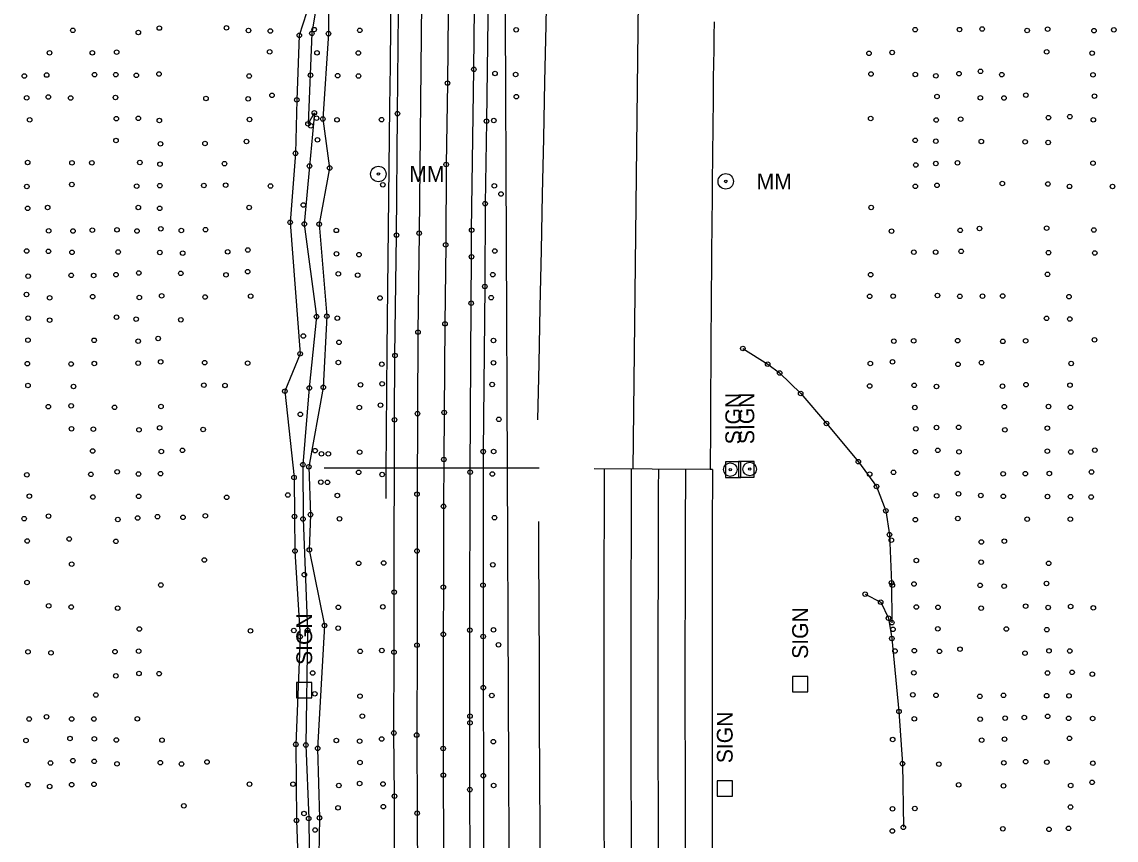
# Model space of a CAD drawing. Extents: x 20503438 to 20508873, y 7964251 to 7984667.
# Drawn here: x 20506380.3 to 20506865.5, y 7965237.1 to 7965600.1 of the extents above; entities that cross this region are included whole.
import ezdxf

# ---------------------------------------------------------------- set-up
doc = ezdxf.new("R2010")
doc.units = 0
for name, color, linetype in [('PhoSignTrussOverhead', 7, 'Continuous'), ('SurBreakLine', 7, 'Continuous'), ('SurDrainageArrowDown', 7, 'Continuous'), ('SurEdgeRoadPaved', 7, 'Continuous'), ('SurEdgeShoulderPaved', 7, 'Continuous'), ('SurGuardRailCable', 7, 'Continuous'), ('SurPointsNonDTM', 7, 'Continuous'), ('SurRoadPoints', 7, 'Continuous'), ('SurSurveyPoints', 7, 'Continuous'), ('SurWetlands', 7, 'Continuous')]:
    doc.layers.add(name, color=color, linetype=linetype)

msp = doc.modelspace()

# ---------------------------------------------------------------- linework, layer by layer
at = {"layer": 'PhoSignTrussOverhead'}
msp.add_line((20506514.44, 7965402.17), (20506609.7, 7965402.17), dxfattribs=at)
at = {"layer": 'SurBreakLine'}
for points in [[(20506660.03, 7966157.63), (20506658.3, 7966009.76), (20506658.04, 7965973.78), (20506656.47, 7965856.82), (20506651.2, 7965401.69)], [(20506522.39, 7965700.71), (20506522, 7965700.32), (20506516.56, 7965699.39), (20506518.84, 7965688.49), (20506515.01, 7965666.88), (20506518.2, 7965645.46), (20506516.16, 7965620.24), (20506516.31, 7965594.85), (20506513.79, 7965556.99), (20506516.81, 7965535.24), (20506512.19, 7965510.34), (20506515.52, 7965469.48), (20506513.97, 7965437.92), (20506507.59, 7965402.71), (20506508.3, 7965381.45), (20506507.78, 7965365.83), (20506514.49, 7965332.27), (20506511.48, 7965277.77), (20506512.31, 7965246.93), (20506511.6, 7965205.59), (20506511.79, 7965203.63)], [(20506511.46, 7965619.33), (20506503.35, 7965594.08), (20506502.22, 7965565.46), (20506501.65, 7965541.77), (20506499.26, 7965511.13), (20506503.71, 7965452.81), (20506496.96, 7965436.26), (20506501.03, 7965397.95), (20506501.18, 7965380.68), (20506501.43, 7965365.34), (20506503.7, 7965327.33), (20506501.82, 7965279.54), (20506502.13, 7965245.82), (20506503.57, 7965205.44), (20506503.7, 7965203.31)], [(20506569.39, 7965603.88), (20506569.1, 7965572.92), (20506568.45, 7965536.8), (20506568.27, 7965501.17), (20506567.94, 7965466.14), (20506567.58, 7965426.78), (20506567.45, 7965405.97), (20506567.32, 7965385.16), (20506567.23, 7965349.31), (20506567.21, 7965328.34), (20506567.14, 7965277.73), (20506567.21, 7965265.93), (20506567.51, 7965206.56), (20506567.54, 7965202.77)]]:
    msp.add_lwpolyline(points, dxfattribs=at)
for radius in [22877.31, 22865.31]:
    msp.add_arc((20529527.68, 7965307.24), radius, 179.763399, 181.192225, dxfattribs=at)
at = {"layer": 'SurDrainageArrowDown'}
for points in [[(20506609.14, 7965423.53), (20506609.66, 7965448.52), (20506610.19, 7965473.52), (20506610.72, 7965498.73), (20506611.24, 7965523.51), (20506611.76, 7965548.5), (20506612.29, 7965573.49), (20506612.82, 7965598.63), (20506613.33, 7965623.29), (20506613.86, 7965648.48), (20506613.96, 7965653.23)], [(20506512.75, 7965618.39), (20506508.94, 7965594.99), (20506507.21, 7965554.81), (20506510.03, 7965559.76), (20506507.85, 7965536.13), (20506505.57, 7965510.38), (20506511, 7965469.31), (20506507.78, 7965437.68), (20506504.95, 7965403.63), (20506505.01, 7965379.53), (20506507.03, 7965330.13), (20506506.23, 7965279.25), (20506507.51, 7965246.68), (20506507.98, 7965205.94), (20506507.99, 7965183.58), (20506506.45, 7965157.25), (20506507.19, 7965112.35), (20506505.61, 7965065.42), (20506505.71, 7965016.95)], [(20506610.82, 7965065.24), (20506610.71, 7965090.24), (20506610.61, 7965115.23), (20506610.51, 7965140.23), (20506610.41, 7965165.23), (20506610.31, 7965190.23), (20506610.21, 7965215.23), (20506610.1, 7965240.23), (20506610, 7965265.23), (20506609.9, 7965290.23), (20506609.8, 7965315.23), (20506609.7, 7965340.23), (20506609.6, 7965365.23), (20506609.54, 7965378.43)]]:
    msp.add_lwpolyline(points, dxfattribs=at)
at = {"layer": 'SurEdgeRoadPaved'}
msp.add_line((20506685.57, 7965401.56), (20506634.11, 7965401.78), dxfattribs=at)
for points in [[(20506562.98, 7966069.12), (20506561.69, 7965956.65), (20506561.36, 7965927.21), (20506561.02, 7965904.12), (20506560.12, 7965843.51), (20506559.8, 7965821.05), (20506559.37, 7965785.5), (20506558.21, 7965668.14), (20506558.03, 7965647.17), (20506557.54, 7965608.72), (20506556.5, 7965506.31), (20506555.98, 7965462.45), (20506555.76, 7965426.25), (20506555.55, 7965390.53), (20506555.55, 7965365.32), (20506555.55, 7965323.6), (20506555.42, 7965283.68), (20506555.63, 7965249), (20506555.73, 7965220.22), (20506555.85, 7965201.63)], [(20506579.33, 7965201.74), (20506579.06, 7965228.35), (20506578.95, 7965259.46), (20506579.02, 7965289.12), (20506579.03, 7965292.09), (20506578.95, 7965330.25), (20506579.12, 7965400.3), (20506579.58, 7965475.25), (20506579.7, 7965495.86), (20506579.77, 7965507.64), (20506580.77, 7965579.04), (20506582.18, 7965713.39), (20506584.15, 7965857.73), (20506584.51, 7965883.12), (20506584.95, 7965922.01), (20506585.27, 7965953.21), (20506585.61, 7965985.81), (20506586.02, 7966017.66)]]:
    msp.add_lwpolyline(points, dxfattribs=at)
for centre, major_axis, start_param, end_param in [((20529528.34, 7965306.75), (15930.49, -16371.54), 3.927809, 3.936499), ((20529528.35, 7965306.75), (16385.16, -15983.87), 3.910449, 3.935387), ((20529528.35, 7965306.75), (16358.96, -15959.17), 3.910476, 3.935414)]:
    msp.add_ellipse(centre, major_axis=major_axis, ratio=0.999988, start_param=start_param, end_param=end_param, dxfattribs=at)
at = {"layer": 'SurEdgeShoulderPaved'}
msp.add_line((20506686.57, 7965401.56), (20506685.57, 7965401.56), dxfattribs=at)
for points in [[(20506545.59, 7965201.59), (20506545.55, 7965219.53), (20506545.56, 7965256.58), (20506545.28, 7965284.63), (20506545.36, 7965320.45), (20506545.43, 7965347.11), (20506545.59, 7965423.56), (20506545.77, 7965452.03), (20506546.43, 7965505.49), (20506546.86, 7965559.32), (20506548.13, 7965680.05), (20506548.89, 7965738.14), (20506549.41, 7965796.65), (20506550.26, 7965848.19), (20506551.65, 7965956.18), (20506552.19, 7965996.51), (20506552.57, 7966028.45), (20506552.68, 7966057.72)], [(20506592.19, 7966059.31), (20506591.79, 7966030.9), (20506591.18, 7965975.25), (20506590.93, 7965954.62), (20506589.59, 7965843.55), (20506588.16, 7965735.35), (20506587.68, 7965699.72), (20506587.42, 7965658.24), (20506587.16, 7965625.38), (20506586.88, 7965601.51), (20506586.38, 7965556.01), (20506585.73, 7965519.42), (20506585.6, 7965482.7), (20506584.9, 7965409.44), (20506584.81, 7965350.17), (20506584.84, 7965327.41), (20506584.92, 7965304.74), (20506584.98, 7965265.69), (20506584.99, 7965225.89), (20506585.23, 7965201.77)]]:
    msp.add_lwpolyline(points, dxfattribs=at)
msp.add_ellipse((20529528.35, 7965306.75), major_axis=(16351.94, -15949.18), ratio=0.999988, start_param=3.910378, end_param=3.935316, dxfattribs=at)
at = {"layer": 'SurGuardRailCable'}
for points in [[(20506613.34, 7964252.79), (20506601.5, 7964822.04), (20506598.64, 7964984.08), (20506597.55, 7965074.02), (20506596.61, 7965201.81), (20506594.34, 7965701.8), (20506594.71, 7965733.27), (20506595.45, 7965806.52), (20506596.03, 7965869.84), (20506597.23, 7965978.92), (20506600.18, 7966186.78), (20506601.51, 7966279.91), (20506601.63, 7966286.68)], [(20506544.5, 7965688.68), (20506544.37, 7965670.68), (20506544.23, 7965652.66), (20506544.02, 7965624.87), (20506543.77, 7965598.66), (20506543.59, 7965580.66), (20506543.41, 7965562.43), (20506542.7, 7965508.66), (20506542.13, 7965454.69), (20506541.73, 7965400.68), (20506541.77, 7965388.69)]]:
    msp.add_lwpolyline(points, dxfattribs=at)
at = {"layer": 'SurPointsNonDTM'}
for centre in [(20506508.31, 7965576.41), (20506508.47, 7965553.92), (20506592.77, 7965523.74), (20506505.14, 7965518.82), (20506505.14, 7965460.72), (20506700.06, 7965455.18), (20506711.06, 7965448.26), (20506716.34, 7965444.32), (20506725.67, 7965435.22), (20506503.78, 7965425.97), (20506591.83, 7965423.75), (20506737.13, 7965421.9), (20506751.27, 7965404.97), (20506498.27, 7965390.18), (20506759.33, 7965393.95), (20506763.44, 7965383.19), (20506765.03, 7965372.58), (20506505.61, 7965354.83), (20506765.93, 7965351.22), (20506754.26, 7965346.22), (20506761.15, 7965342.67), (20506764.62, 7965335.54), (20506766.12, 7965333.53), (20506591.69, 7965323.75), (20506766.09, 7965326.51), (20506509.29, 7965311.22), (20506769.25, 7965294.11), (20506770.8, 7965270.97), (20506505.4, 7965248.86), (20506771.22, 7965242.76)]:
    msp.add_circle(centre, 1, dxfattribs=at)
at = {"layer": 'SurRoadPoints'}
for points in [[(20506699.21, 7965401.42), (20506699.21, 7965401.42), (20506699.21, 7965404.85), (20506692.35, 7965404.85), (20506692.35, 7965397.99), (20506699.21, 7965397.99), (20506699.21, 7965401.42)], [(20506705.03, 7965401.56), (20506705.03, 7965401.56), (20506705.03, 7965404.99), (20506698.17, 7965404.99), (20506698.17, 7965398.13), (20506705.03, 7965398.13), (20506705.03, 7965401.56)], [(20506728.85, 7965306.3), (20506728.85, 7965306.3), (20506728.85, 7965309.73), (20506721.99, 7965309.73), (20506721.99, 7965302.87), (20506728.85, 7965302.87), (20506728.85, 7965306.3)], [(20506508.96, 7965303.6), (20506508.96, 7965303.6), (20506508.96, 7965307.03), (20506502.1, 7965307.03), (20506502.1, 7965300.17), (20506508.96, 7965300.17), (20506508.96, 7965303.6)], [(20506695.44, 7965260), (20506695.44, 7965260), (20506695.44, 7965263.43), (20506688.58, 7965263.43), (20506688.58, 7965256.57), (20506695.44, 7965256.57), (20506695.44, 7965260)]]:
    msp.add_lwpolyline(points, dxfattribs=at)
for centre, radius in [((20506538.42, 7965532.57), 3.43), ((20506538.42, 7965532.57), 0.571), ((20506692.45, 7965529.31), 3.43), ((20506692.45, 7965529.31), 0.571), ((20506694.48, 7965401.45), 3), ((20506694.48, 7965401.45), 0.5), ((20506703.08, 7965401.68), 3), ((20506703.08, 7965401.68), 0.5)]:
    msp.add_circle(centre, radius, dxfattribs=at)
at = {"layer": 'SurSurveyPoints'}
for centre in [(20506402.92, 7965596.33), (20506431.99, 7965595.39), (20506441.28, 7965597.32), (20506471.04, 7965597.4), (20506480.83, 7965596.23), (20506490.49, 7965596.02), (20506503.35, 7965594.08), (20506508.94, 7965594.99), (20506509.95, 7965596.65), (20506516.31, 7965594.85), (20506530.15, 7965596.29), (20506599.52, 7965596.57), (20506776.44, 7965596.6), (20506796.13, 7965596.65), (20506806.15, 7965596.88), (20506826.08, 7965596.23), (20506835.19, 7965596.83), (20506855.75, 7965596.19), (20506864.55, 7965596.56), (20506392.61, 7965586.34), (20506411.6, 7965586.37), (20506422.33, 7965586.63), (20506490.22, 7965586.78), (20506511.17, 7965586.37), (20506529.55, 7965586.26), (20506755.95, 7965586.12), (20506766.23, 7965586.51), (20506834.78, 7965586.8), (20506854.91, 7965586.22), (20506580.77, 7965579.04), (20506381.43, 7965576.07), (20506391.34, 7965576.47), (20506412.56, 7965576.65), (20506421.96, 7965576.62), (20506431.07, 7965576.38), (20506441.14, 7965576.94), (20506481.1, 7965576.05), (20506520.34, 7965576.18), (20506529.59, 7965576.07), (20506590.14, 7965577.19), (20506599.29, 7965576.74), (20506756.84, 7965576.92), (20506776.5, 7965576.76), (20506785.63, 7965576.15), (20506795.91, 7965577.1), (20506805.42, 7965578.14), (20506814.85, 7965576.63), (20506855.28, 7965576.58), (20506569.1, 7965572.92), (20506382.47, 7965566.37), (20506392.04, 7965566.75), (20506401.94, 7965566.32), (20506421.82, 7965566.51), (20506461.94, 7965566.1), (20506480.69, 7965565.9), (20506491.24, 7965567.49), (20506502.22, 7965565.46), (20506599.61, 7965566.88), (20506786.11, 7965566.96), (20506805.37, 7965566.4), (20506815.83, 7965566.33), (20506825.54, 7965567.59), (20506855.93, 7965567.14), (20506510.03, 7965559.76), (20506383.81, 7965556.6), (20506422.22, 7965557.16), (20506431.94, 7965557.25), (20506441.3, 7965556.29), (20506481.3, 7965556.76), (20506507.21, 7965554.81), (20506511, 7965557.35), (20506513.79, 7965556.99), (20506520.05, 7965556.65), (20506539.83, 7965556.71), (20506546.86, 7965559.32), (20506586.38, 7965556.01), (20506589.58, 7965556.29), (20506756.73, 7965557.2), (20506785.78, 7965556.51), (20506796.59, 7965556.91), (20506835.53, 7965557.58), (20506845.03, 7965558.02), (20506855.42, 7965556.64), (20506422.06, 7965547.42), (20506441.77, 7965545.98), (20506461.5, 7965546.13), (20506479.91, 7965546.99), (20506511.38, 7965547.76), (20506776.48, 7965547.51), (20506785.62, 7965547.12), (20506805.75, 7965547.03), (20506825.2, 7965546.85), (20506835.42, 7965546.56), (20506501.65, 7965541.77), (20506382.89, 7965537.71), (20506402.52, 7965537.53), (20506411.37, 7965537.53), (20506432.65, 7965537.68), (20506441.57, 7965536.91), (20506470.16, 7965537.17), (20506507.85, 7965536.13), (20506516.81, 7965535.24), (20506568.45, 7965536.8), (20506776.7, 7965536.59), (20506785.61, 7965537.21), (20506795.23, 7965537.54), (20506855.29, 7965537.39), (20506382.5, 7965527.04), (20506402.47, 7965527.94), (20506431.23, 7965527.18), (20506441.51, 7965527.4), (20506461.04, 7965527.47), (20506470.72, 7965527.6), (20506490.58, 7965527.23), (20506540.39, 7965527.8), (20506589.82, 7965527.32), (20506776.5, 7965527.12), (20506786.11, 7965527.55), (20506815.07, 7965528.36), (20506835.3, 7965528.15), (20506844.86, 7965527.08), (20506863.97, 7965527.07), (20506382.89, 7965517.37), (20506391.74, 7965517.69), (20506431.95, 7965517.75), (20506441.46, 7965517.34), (20506481.09, 7965517.75), (20506585.73, 7965519.42), (20506756.94, 7965517.75), (20506499.26, 7965511.13), (20506392.23, 7965507.39), (20506402.97, 7965507.27), (20506411.54, 7965507.67), (20506422.52, 7965507.84), (20506431.4, 7965507.3), (20506441.92, 7965508.29), (20506451.03, 7965507.54), (20506461.74, 7965507.86), (20506505.57, 7965510.38), (20506512.19, 7965510.34), (20506519.76, 7965507.56), (20506556.5, 7965506.31), (20506579.77, 7965507.64), (20506765.97, 7965507.23), (20506796.42, 7965507.59), (20506804.94, 7965508.39), (20506834.74, 7965508.55), (20506855.66, 7965507.75), (20506546.43, 7965505.49), (20506382.44, 7965498.45), (20506392.1, 7965498.27), (20506402.58, 7965497.82), (20506423.04, 7965497.98), (20506441.51, 7965497.79), (20506451.66, 7965497.5), (20506471.61, 7965498.09), (20506480.52, 7965498.84), (20506519.82, 7965497.18), (20506529.84, 7965496.81), (20506568.27, 7965501.17), (20506590.03, 7965498.4), (20506775.85, 7965497.91), (20506785.54, 7965497.94), (20506796.84, 7965498.31), (20506835.57, 7965497.71), (20506856.09, 7965497.57), (20506579.7, 7965495.86), (20506383.13, 7965487.25), (20506402.22, 7965487.63), (20506412.14, 7965487.53), (20506422.07, 7965487.96), (20506432.16, 7965488.68), (20506450.79, 7965488.55), (20506470.82, 7965487.82), (20506480.48, 7965489.24), (20506520.63, 7965488.28), (20506529.26, 7965487.74), (20506589.14, 7965487.95), (20506756.69, 7965487.94), (20506835.11, 7965488.07), (20506585.6, 7965482.7), (20506382.36, 7965479.14), (20506392.62, 7965477.64), (20506411.74, 7965478.14), (20506432.39, 7965477.81), (20506442.3, 7965478.54), (20506461.57, 7965478.01), (20506481.8, 7965478.41), (20506539.12, 7965477.57), (20506588.44, 7965477.7), (20506756.26, 7965478.29), (20506766.65, 7965478.41), (20506786.32, 7965478.68), (20506796.25, 7965478.34), (20506806.31, 7965478.39), (20506815.23, 7965478.45), (20506844.64, 7965478.15), (20506579.58, 7965475.25), (20506383.11, 7965468.66), (20506392.63, 7965467.72), (20506422.28, 7965469.05), (20506430.97, 7965468.21), (20506450.83, 7965467.92), (20506511, 7965469.31), (20506515.52, 7965469.48), (20506520.19, 7965468.65), (20506834.71, 7965468.54), (20506845, 7965468.25), (20506555.98, 7965462.45), (20506567.94, 7965466.14), (20506383.01, 7965458.87), (20506412.4, 7965458.83), (20506431.92, 7965458.41), (20506440.78, 7965459.64), (20506520.93, 7965457.88), (20506589.43, 7965458.73), (20506767, 7965458.46), (20506775.81, 7965458.58), (20506795.28, 7965458.65), (20506815.31, 7965458.32), (20506825.43, 7965458.57), (20506855.98, 7965459.01), (20506503.71, 7965452.81), (20506382.78, 7965448.42), (20506402.15, 7965448.32), (20506412.43, 7965448.49), (20506431.88, 7965448.68), (20506441.88, 7965449.23), (20506461.38, 7965448.92), (20506480.44, 7965448.66), (20506520.68, 7965448.95), (20506539.92, 7965448.2), (20506545.77, 7965452.03), (20506589.44, 7965448.84), (20506756.55, 7965448.51), (20506766.38, 7965449.23), (20506795.46, 7965448.18), (20506805.87, 7965448.86), (20506845.63, 7965448.54), (20506383.01, 7965438.77), (20506403.24, 7965438.34), (20506461.04, 7965438.89), (20506470.4, 7965438.78), (20506530.52, 7965439.09), (20506540.06, 7965439.51), (20506588.88, 7965439.2), (20506756.3, 7965438.53), (20506776.03, 7965438.84), (20506785.88, 7965438.31), (20506815.16, 7965438.43), (20506825.57, 7965439.13), (20506845.09, 7965438.87), (20506496.96, 7965436.26), (20506507.78, 7965437.68), (20506513.97, 7965437.92), (20506392.03, 7965429.37), (20506402.2, 7965429.75), (20506421.43, 7965429.05), (20506442.05, 7965429.46), (20506529.97, 7965429), (20506539.32, 7965430.02), (20506776.28, 7965428.97), (20506815.98, 7965429.4), (20506835.56, 7965429.42), (20506845.25, 7965429.05), (20506555.76, 7965426.25), (20506567.58, 7965426.78), (20506402.34, 7965419.57), (20506412.03, 7965419.37), (20506432.25, 7965419.08), (20506441.42, 7965420.01), (20506460.68, 7965419.23), (20506545.59, 7965423.56), (20506776.72, 7965419.53), (20506785.89, 7965420.1), (20506795.73, 7965420.2), (20506816.23, 7965419.1), (20506835.06, 7965419.8), (20506411.72, 7965409.69), (20506442.15, 7965409.47), (20506451.53, 7965409.97), (20506510.36, 7965409.82), (20506530.11, 7965409.18), (20506584.9, 7965409.44), (20506589.53, 7965409.5), (20506776.5, 7965409.42), (20506786.46, 7965410.03), (20506795.87, 7965409.35), (20506835.08, 7965409.64), (20506845.46, 7965409.29), (20506856.13, 7965410.06), (20506513.17, 7965408.45), (20506516.2, 7965408.44), (20506567.45, 7965405.97), (20506410.93, 7965399.33), (20506422.61, 7965400.47), (20506432.04, 7965399.47), (20506441.82, 7965399.64), (20506504.95, 7965403.63), (20506507.59, 7965402.71), (20506529.66, 7965400.27), (20506579.12, 7965400.3), (20506588.97, 7965399.47), (20506756.25, 7965399.46), (20506766.84, 7965400.24), (20506795.15, 7965399.8), (20506815.44, 7965399.58), (20506825.31, 7965399.64), (20506835.95, 7965399.7), (20506854.63, 7965400.36), (20506382.55, 7965399.13), (20506501.03, 7965397.95), (20506512.89, 7965395.9), (20506515.83, 7965395.79), (20506540.11, 7965399.24), (20506383.64, 7965389.64), (20506432.09, 7965389.6), (20506520.23, 7965389.94), (20506555.55, 7965390.53), (20506776.53, 7965390.45), (20506786.01, 7965389.8), (20506795.66, 7965390.69), (20506805.54, 7965390), (20506815.53, 7965389.6), (20506411.83, 7965389.29), (20506471.16, 7965389.14), (20506567.32, 7965385.16), (20506835.14, 7965389.48), (20506845.35, 7965389.44), (20506854.5, 7965389.3), (20506392.16, 7965380.83), (20506431.66, 7965379.96), (20506440.47, 7965380.55), (20506451.8, 7965380.26), (20506461.69, 7965380.93), (20506501.18, 7965380.68), (20506508.3, 7965381.45), (20506589.89, 7965380.12), (20506381.33, 7965379.67), (20506422.86, 7965379.33), (20506505.01, 7965379.53), (20506521.16, 7965379.63), (20506776.55, 7965379.22), (20506795.35, 7965379.77), (20506826.14, 7965379.45), (20506845.23, 7965379.46), (20506401.33, 7965370.69), (20506382.71, 7965369.8), (20506422.02, 7965369.65), (20506501.43, 7965365.34), (20506507.78, 7965365.83), (20506765.87, 7965370.15), (20506805.79, 7965369.32), (20506815.98, 7965369.67), (20506461.21, 7965361.35), (20506555.55, 7965365.32), (20506776.98, 7965361.16), (20506402.42, 7965359.48), (20506529.68, 7965359.89), (20506540.77, 7965360.03), (20506589.17, 7965359.24), (20506805.72, 7965360.37), (20506835.61, 7965359.87), (20506382.59, 7965351.38), (20506834.67, 7965350.96), (20506441.95, 7965350.25), (20506545.43, 7965347.11), (20506567.23, 7965349.31), (20506584.81, 7965350.17), (20506766.35, 7965350.15), (20506775.94, 7965350.7), (20506805.23, 7965350.13), (20506815.88, 7965349.75), (20506392.24, 7965341.01), (20506402.22, 7965340.49), (20506422.83, 7965340), (20506520.66, 7965340.37), (20506540.37, 7965340.55), (20506776.99, 7965340.51), (20506786.55, 7965340.32), (20506805.72, 7965339.97), (20506825.44, 7965340.83), (20506835.39, 7965340.31), (20506845.38, 7965340.74), (20506855.43, 7965340.09), (20506514.49, 7965332.27), (20506432.41, 7965330.71), (20506481.68, 7965329.89), (20506500.92, 7965330.07), (20506503.7, 7965327.33), (20506507.03, 7965330.13), (20506520.59, 7965331.14), (20506567.21, 7965328.34), (20506578.95, 7965330.25), (20506584.84, 7965327.41), (20506589.45, 7965330.33), (20506766.63, 7965330.58), (20506786.47, 7965330.82), (20506816.86, 7965330.72), (20506834.83, 7965330.46), (20506555.55, 7965323.6), (20506796.3, 7965321.76), (20506383.07, 7965320.6), (20506393.23, 7965320.17), (20506421.65, 7965320.71), (20506432.12, 7965320.91), (20506530.34, 7965320.81), (20506539.93, 7965321.21), (20506545.36, 7965320.45), (20506767.5, 7965321.01), (20506776.08, 7965321.14), (20506787.21, 7965320.82), (20506825.17, 7965320.02), (20506835.76, 7965321.02), (20506845, 7965321.01), (20506422, 7965309.94), (20506432.24, 7965311.02), (20506441.18, 7965310.91), (20506775.82, 7965311.29), (20506835.14, 7965311.21), (20506846.04, 7965311.54), (20506855.01, 7965310.73), (20506584.92, 7965304.74), (20506413.11, 7965301.48), (20506510.21, 7965302), (20506530.26, 7965300.93), (20506588.69, 7965301.25), (20506775.39, 7965301.52), (20506785.7, 7965301.34), (20506805.13, 7965300.88), (20506815.63, 7965301.3), (20506834.73, 7965301.13), (20506844.67, 7965301.12), (20506383.56, 7965290.78), (20506391.25, 7965291.81), (20506402.4, 7965290.81), (20506412.26, 7965290.83), (20506431.55, 7965290.91), (20506531.28, 7965292.06), (20506579.02, 7965289.12), (20506579.03, 7965292.09), (20506776.05, 7965290.92), (20506805.27, 7965290.72), (20506816.36, 7965291.21), (20506824.82, 7965291.48), (20506835.19, 7965292.01), (20506844.5, 7965291.12), (20506855.12, 7965291.05), (20506545.28, 7965284.63), (20506555.42, 7965283.68), (20506382.15, 7965281.28), (20506401.64, 7965282.13), (20506412.47, 7965282.02), (20506422.2, 7965281.49), (20506442.45, 7965281.45), (20506501.82, 7965279.54), (20506506.23, 7965279.25), (20506519.79, 7965281.31), (20506530.11, 7965280.96), (20506539.89, 7965281.92), (20506589.37, 7965280.78), (20506766.49, 7965281.68), (20506805.94, 7965281.43), (20506816.09, 7965281.87), (20506844.85, 7965282.22), (20506511.48, 7965277.77), (20506567.14, 7965277.73), (20506393, 7965271.3), (20506402.95, 7965272.35), (20506412.41, 7965272.04), (20506422.48, 7965270.93), (20506441.72, 7965271.41), (20506451.11, 7965270.85), (20506462.45, 7965271.74), (20506530.26, 7965271.5), (20506786.96, 7965270.8), (20506815.73, 7965271.33), (20506825.44, 7965271.9), (20506834.85, 7965271.68), (20506855.26, 7965271.19), (20506567.21, 7965265.93), (20506584.98, 7965265.69), (20506382.98, 7965261.65), (20506392.67, 7965260.89), (20506402.4, 7965261.69), (20506412.3, 7965261.8), (20506481.27, 7965261.89), (20506500.53, 7965261.93), (20506520.87, 7965261.33), (20506530.08, 7965262.19), (20506540.48, 7965261.95), (20506578.95, 7965259.46), (20506589.52, 7965261.33), (20506795.74, 7965261.64), (20506815.61, 7965261.15), (20506845.43, 7965261.3), (20506854.9, 7965262.7), (20506545.56, 7965256.58), (20506452.16, 7965252.29), (20506520.54, 7965251.44), (20506540.6, 7965251.95), (20506555.63, 7965249), (20506766.41, 7965250.95), (20506776.29, 7965251.11), (20506845.33, 7965251.77), (20506502.13, 7965245.82), (20506507.51, 7965246.68), (20506512.31, 7965246.93), (20506510.36, 7965241.54), (20506766.35, 7965241.12), (20506815.33, 7965242.11), (20506835.81, 7965241.89), (20506844.46, 7965242.33)]:
    msp.add_circle(centre, 1, dxfattribs=at)
at = {"layer": 'SurWetlands'}
for points in [[(20506700.06, 7965455.18), (20506711.06, 7965448.26), (20506716.34, 7965444.32), (20506725.67, 7965435.22), (20506737.13, 7965421.9), (20506751.27, 7965404.97), (20506759.33, 7965393.95), (20506763.44, 7965383.19), (20506765.03, 7965372.58), (20506765.93, 7965351.22), (20506766.12, 7965333.53)], [(20506754.26, 7965346.22), (20506761.15, 7965342.67), (20506764.62, 7965335.54), (20506766.09, 7965326.51), (20506769.25, 7965294.11), (20506770.8, 7965270.97), (20506771.22, 7965242.76)]]:
    msp.add_lwpolyline(points, dxfattribs=at)

# ---------------------------------------------------------------- texts
at = {"layer": 'SurRoadPoints'}
for s, rotation, p in [('MM', 360, (20506552.13, 7965529.08)), ('MM', 360, (20506706.16, 7965525.81)), ('SIGN', 90, (20506699.28, 7965412.63)), ('SIGN', 90, (20506705.1, 7965412.77)), ('SIGN', 90, (20506728.92, 7965317.51)), ('SIGN', 90, (20506509.03, 7965314.81)), ('SIGN', 90, (20506695.51, 7965271.21))]:
    msp.add_text(s, height=6.995, rotation=rotation, dxfattribs=at).set_placement(p)

doc.saveas('drawing.dxf')
